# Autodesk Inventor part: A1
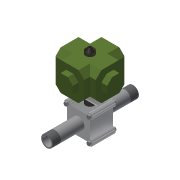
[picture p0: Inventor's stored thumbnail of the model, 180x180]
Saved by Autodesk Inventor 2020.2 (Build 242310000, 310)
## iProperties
Created: 2014-08
Part Number: A1
Material: Ogólny
Document SubType Name: Modeling
Designer: F.Stasiak
Density: 1 g/cm^3
Appearance: Domyślna
Categories: <MemberInstance><Categories><Category DisplayName="" InternalName="4347fa0f-2144-441d-94cd-e3e15c92b736" Mnemonic="TUBEANDPIPE"><CategoryParameter DisplayName="
Catalog Web Link: www.expertbooks.pl
Manager: www.cadconsulting.pl
Company: Fabian Stasiak CAD Consulting
Author: F.Stasiak
Subject: Zbiór ćwiczeń. Autodesk Inventor 2020. Kurs Professional
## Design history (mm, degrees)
sketch "Szkic2"
  geometry: C1 r 10.22 at (0, 0); 1 further point
  constraints: 1 centre point, 1 coincident
  dimensions: "d1" = 20.44 diameter of C1
extrude "Wyciągnięcie proste1" new body sketch "Szkic2" stored distance "d3" = 150; taper "d4" = 0 deg
sketch "Szkic3"
  geometry: L1 (20, -20)-(-20, -20); L2 (-20, -20)-(-20, 20); L3 (-20, 20)-(20, 20); L4 (20, 20)-(20, -20); L5 (20, -20)-(-20, 20); L6 (-20, -20)-(20, 20); C1 r 5 at (20, 20); C2 r 5 at (-20, 20); C3 r 5 at (20, -20); C4 r 5 at (-20, -20); 1 further point
  constraints: 12 end point, 4 centre point, 4 coincident, 3 equal radius, 2 midpoint, 2 parallel, 1 horizontal, 1 perpendicular
  dimensions: "d5" = 40 distance of L2.end L3.end; "d6" = 10 diameter of C1; "d55" = 40 distance of L1.end L2.end (= d5)
extrude "Wyciągnięcie proste2" join sketch "Szkic3" stored distance "d7" = 40; taper "d8" = 0 deg
sketch "Szkic4"
  geometry: L1 (-15, -20)-(15, -20) reference; L2 (20, -15)-(20, 15) reference; L3 (15, 20)-(-15, 20) reference; L4 (-20, 15)-(-20, -15) reference; L5 (-18.268, 23)-(-16.536, 20); L6 (-16.536, 20)-(-18.268, 17); L7 (-18.268, 17)-(-21.732, 17); L8 (-21.732, 17)-(-23.464, 20); L9 (-23.464, 20)-(-21.732, 23); L10 (-21.732, 23)-(-18.268, 23); L11 (21.732, 23)-(23.464, 20); L12 (23.464, 20)-(21.732, 17); L13 (21.732, 17)-(18.268, 17); L14 (18.268, 17)-(16.536, 20); L15 (16.536, 20)-(18.268, 23); L16 (18.268, 23)-(21.732, 23); L17 (21.732, -17)-(23.464, -20); L18 (23.464, -20)-(21.732, -23); L19 (21.732, -23)-(18.268, -23); L20 (18.268, -23)-(16.536, -20); L21 (16.536, -20)-(18.268, -17); L22 (18.268, -17)-(21.732, -17); L23 (-18.289, -16.988)-(-16.536, -19.975); L24 (-16.536, -19.975)-(-18.247, -22.988); L25 (-18.247, -22.988)-(-21.711, -23.012); L26 (-21.711, -23.012)-(-23.464, -20.025); L27 (-23.464, -20.025)-(-21.753, -17.012); L28 (-21.753, -17.012)-(-18.289, -16.988); C1 r 10.22 at (0, 0) reference; A1 r 5 centre (20, -20) between (15, -20) and (20, -15) reference; A2 r 5 centre (20, 20) between (20, 15) and (15, 20) reference; A3 r 5 centre (-20, 20) between (-15, 20) and (-20, 15) reference; A4 r 5 centre (-20, -20) between (-20, -15) and (-15, -20) reference; 6 further points
  constraints: 48 end point, 4 coincident, 1 midpoint, 1 point on line, 52 other
  dimensions: "d9" = 6 distance between parallel lines of L10 L7; "d10" = 6 distance between parallel lines of L13 L16; "d11" = 6 distance between parallel lines of L25 L28 (= d9); "d12" = 6 distance between parallel lines of L22 L19 (= d11)
extrude "Wyciągnięcie proste3" join sketch "Szkic4" distance "d13" = 3; taper "d14" = 0 deg
mirror "Odbicie lustrzane1"
sketch "Szkic5"
  geometry: C1 r 7.5 at (15, 20); 1 further point
  constraints: 1 centre point, 1 coincident
  dimensions: "d15" = 15 diameter of C1
extrude "Wyciągnięcie proste4" join sketch "Szkic5" distance "d16" = 25; taper "d17" = 0 deg
sketch "Szkic6"
  geometry: L1 (-35, 25)-(35, 25); L2 (35, 25)-(35, -25); L3 (35, -25)-(-35, -25); L4 (-35, -25)-(-35, 25); L5 (-35, 25)-(35, -25); L6 (35, 25)-(-35, -25); 1 further point
  constraints: 12 end point, 2 midpoint, 2 parallel, 1 horizontal, 1 perpendicular
  dimensions: "d18" = 70 distance of L2.end L3.end; "d19" = 50 distance of L1.end L2.end
extrude "Wyciągnięcie proste5" join sketch "Szkic6" distance "d20" = 50; taper "d21" = 0 deg
chamfer "Faza1" distance "d22" = 10; stored, may be unused: second distance "d23" = 2, angle "d24" = 45 deg
sketch "Szkic7"
  geometry: L1 (25, 35)-(-25, 35); L2 (-25, 35)-(-25, -35); L3 (-25, -35)-(25, -35); L4 (25, -35)-(25, 35); L5 (25, 35)-(-25, -35); L6 (-25, 35)-(25, -35); 1 further point
  constraints: 12 end point, 2 midpoint, 2 parallel, 1 horizontal, 1 perpendicular
  dimensions: "d25" = 50 distance of L2.end L3.end (= d19); "d26" = 70 distance of L1.end L2.end (= d18)
extrude "Wyciągnięcie proste6" join sketch "Szkic7" distance "d27" = 50 (= d20); taper "d28" = 0 deg
chamfer "Faza2" distance "d29" = 10; stored, may be unused: second distance "d30" = 2, angle "d31" = 45 deg
node "Płaszczyzna konstrukcyjna1"
sketch "Szkic8"
  geometry: L1 (40, 7.5)-(-10, 7.5); L2 (-10, 7.5)-(-10, 32.5); L3 (-10, 32.5)-(40, 32.5); L4 (40, 32.5)-(40, 7.5); L5 (40, 7.5)-(-10, 32.5); L6 (-10, 7.5)-(40, 32.5); 1 further point
  constraints: 12 end point, 2 midpoint, 2 parallel, 1 horizontal, 1 perpendicular
  dimensions: "d33" = 50 distance of L2.end L3.end; "d34" = 25 distance of L1.end L2.end
extrude "Wyciągnięcie proste7" join sketch "Szkic8" stored distance "d35" = 2; taper "d36" = 0 deg
sketch "Szkic9"
  geometry: C1 r 7.5 at (0, 0); 1 further point
  constraints: 1 centre point, 1 coincident
  dimensions: "d37" = 15 diameter of C1
extrude "Wyciągnięcie proste8" join sketch "Szkic9" distance "d38" = 10; taper "d39" = 0 deg
chamfer "Faza3" distance "d40" = 5; stored, may be unused: second distance "d41" = 2, angle "d42" = 45 deg
sketch "Szkic10"
  geometry: L1 (-10, -10)-(0, 0) reference; L2 (-10, -10)-(-10, -40) reference; L3 (0, -50)-(-10, -40) reference; L4 (30, -50)-(0, -50) reference; L5 (40, -40)-(30, -50) reference; L6 (40, -10)-(40, -40) reference; L7 (30, 0)-(40, -10) reference; L8 (0, 0)-(30, 0) reference; L9 (30, -31.213)-(21.213, -40); L10 (21.213, -40)-(8.787, -40); L11 (8.787, -40)-(0, -31.213); L12 (0, -31.213)-(0, -18.787); L13 (0, -18.787)-(8.787, -10); L14 (8.787, -10)-(21.213, -10); L15 (21.213, -10)-(30, -18.787); L16 (30, -18.787)-(30, -31.213); 2 further points
  constraints: 16 end point, 17 other
extrude "Wyciągnięcie proste9" join sketch "Szkic10" distance "d43" = 10; taper "d44" = 0 deg
pattern_circular "Szyk kołowy1" dims angle "d46" = 360 deg
sketch "Szkic11"
  geometry: C1 r 8.05 at (0, 0); 1 further point
  constraints: 1 centre point, 1 coincident
  dimensions: "d48" = 16.1 diameter of C1
extrude "Wyciągnięcie proste10" cut sketch "Szkic11" extent not by distance; stored distance "d49" = 10; taper "d50" = 0 deg
feature "Gwint1" dims "d51" = 14, "d52" = 0
feature "Gwint2" dims "d53" = 14, "d54" = 0
node "Punkt konstrukcyjny1"
node "Punkt konstrukcyjny2"
node "Oś konstrukcyjna1"
node "Oś konstrukcyjna2"
node "Bryła1"
node "Pętla rzutowana1"
node "Pętla rzutowana2"
other parameters: "d56" = 15
